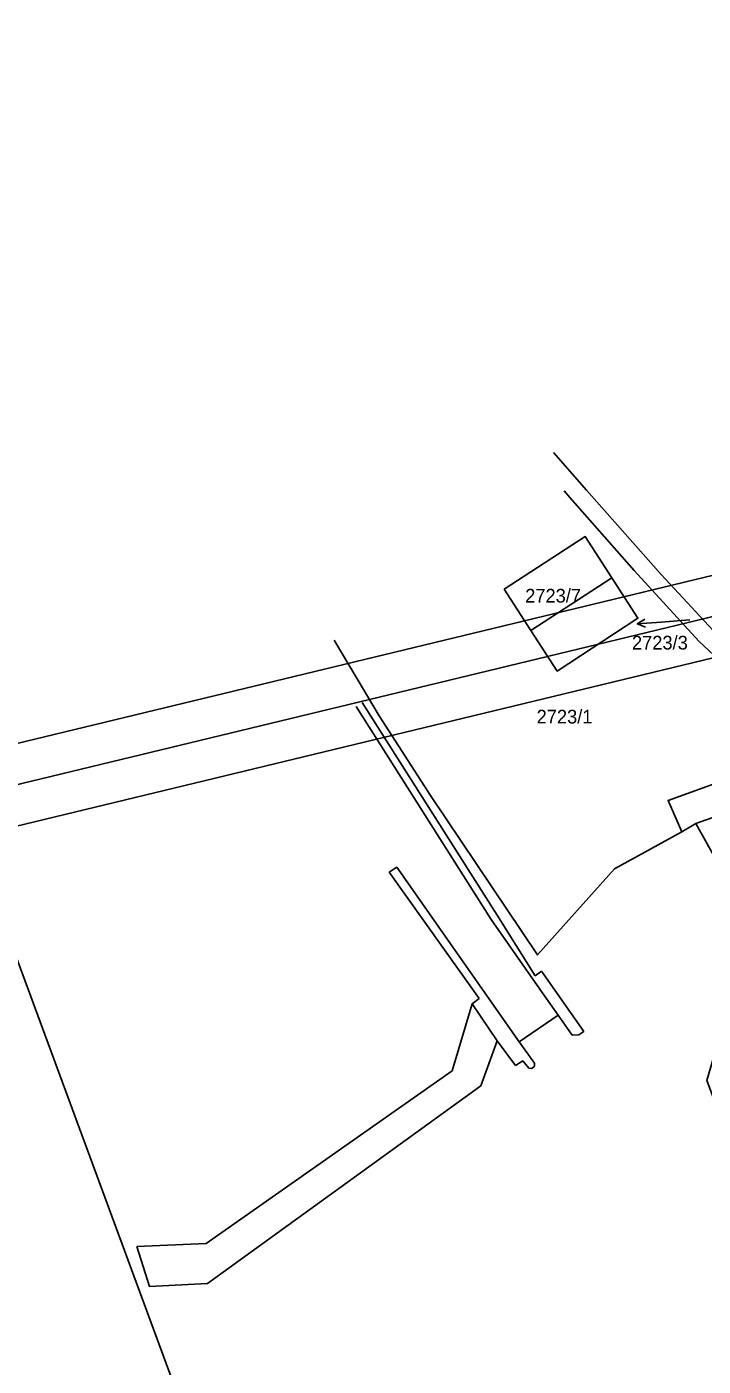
# Model space of a CAD drawing. Extents: x -738085 to -734306, y -1122197 to -1119753.
# Drawn here: x -735309.7 to -735225.5, y -1120249.4 to -1120082.8 of the extents above; entities that cross this region are included whole.
import ezdxf

# ---------------------------------------------------------------- set-up
doc = ezdxf.new("R2010")
doc.units = 0
for name, color, linetype in [('Hranice parcel', 7, 'Continuous'), ('Parcelní čísla', 7, 'Continuous'), ('Pop  PČ popisy', 7, 'Continuous'), ('Vnitřní kresba', 7, 'Continuous'), ('Vrstva 1', 7, 'Continuous')]:
    doc.layers.add(name, color=color, linetype=linetype)

msp = doc.modelspace()

# ---------------------------------------------------------------- linework, layer by layer
at = {"layer": 'Hranice parcel'}
for q in [(-735214.89, -1120177.8), (-735228.19, -1120182.96)]:
    msp.add_line((-735226.43, -1120181.92), q, dxfattribs=at)
for points in [[(-735290.18, -1120254.92), (-735317.57, -1120180.85), (-735339.79, -1120142.5), (-735361.49, -1120104.8), (-735379.62, -1120073.45), (-735392.28, -1120051.31)], [(-735290.18, -1120254.92), (-735317.57, -1120180.85), (-735339.79, -1120142.5), (-735361.49, -1120104.8), (-735379.62, -1120073.45), (-735392.28, -1120051.31)], [(-735193.9, -1120180.77), (-735196.33, -1120174.06), (-735197.48, -1120172.4), (-735199.22, -1120171.31), (-735200.58, -1120170.92), (-735204.03, -1120169.95), (-735208.93, -1120168.56), (-735215.43, -1120165.33), (-735220.17, -1120161.76), (-735223.18, -1120159.07), (-735230.74, -1120150.98), (-735240.02, -1120140.46), (-735244.13, -1120135.8)], [(-735207.77, -1120171.07), (-735211.09, -1120169.95), (-735216.45, -1120167.23), (-735220.95, -1120164.02), (-735226.04, -1120159.26), (-735234.12, -1120150.47), (-735242.12, -1120141.37), (-735242.83, -1120140.56)], [(-735250.29, -1120152.79), (-735240.22, -1120146.25), (-735236.9, -1120151.38), (-735233.63, -1120156.4), (-735243.68, -1120162.97), (-735246.97, -1120157.91), (-735250.29, -1120152.79)], [(-735228.19, -1120182.96), (-735236.55, -1120187.57), (-735246.14, -1120198.27), (-735259.45, -1120178.43), (-735265.84, -1120168.52), (-735271.46, -1120159.13)], [(-735228.19, -1120182.96), (-735229.89, -1120179.07), (-735207.77, -1120171.07)], [(-735226.43, -1120181.92), (-735221.97, -1120189.91), (-735220.76, -1120199.13), (-735225.06, -1120213.91), (-735220.47, -1120226.11), (-735217.93, -1120231.25)]]:
    msp.add_lwpolyline(points, dxfattribs=at)
at = {"layer": 'Pop  PČ popisy'}
for p, q in [((-735233.73, -1120157.08), (-735232.77, -1120156.51)), ((-735230.74, -1120156.87), (-735233.73, -1120157.08)), ((-735233.73, -1120157.08), (-735232.7, -1120157.51)), ((-735227.16, -1120156.6), (-735230.74, -1120156.87))]:
    msp.add_line(p, q, dxfattribs=at)
at = {"layer": 'Vnitřní kresba'}
for p, q in [((-735236.9, -1120151.38), (-735246.97, -1120157.91)), ((-735268.71, -1120167.38), (-735251.91, -1120193.87)), ((-735267.95, -1120166.9), (-735251.17, -1120193.35)), ((-735264.59, -1120187.99), (-735263.64, -1120187.35)), ((-735263.64, -1120187.35), (-735248.42, -1120209.08)), ((-735264.59, -1120187.99), (-735253.4, -1120203.71)), ((-735251.91, -1120193.87), (-735245.55, -1120202.96)), ((-735251.17, -1120193.35), (-735246.44, -1120200.88)), ((-735246.44, -1120200.88), (-735245.64, -1120200.28)), ((-735245.64, -1120200.28), (-735240.37, -1120207.79)), ((-735256.75, -1120212.71), (-735254.25, -1120204.36)), ((-735254.25, -1120204.36), (-735253.4, -1120203.71)), ((-735254.25, -1120204.36), (-735251.16, -1120208.96)), ((-735245.55, -1120202.96), (-735243.58, -1120205.77)), ((-735248.42, -1120209.08), (-735243.58, -1120205.77)), ((-735243.58, -1120205.77), (-735241.84, -1120208.25)), ((-735240.98, -1120208.23), (-735240.37, -1120207.79)), ((-735253.19, -1120214.56), (-735251.16, -1120208.96)), ((-735251.16, -1120208.96), (-735248.88, -1120212.03)), ((-735248.42, -1120209.08), (-735246.51, -1120211.75)), ((-735241.84, -1120208.25), (-735240.98, -1120208.23)), ((-735287.37, -1120234.17), (-735256.75, -1120212.71)), ((-735248.88, -1120212.03), (-735247.98, -1120211.43)), ((-735247.98, -1120211.43), (-735247.23, -1120212.35)), ((-735247.23, -1120212.35), (-735246.86, -1120212.39)), ((-735246.86, -1120212.39), (-735246.51, -1120212.13)), ((-735246.51, -1120211.75), (-735246.51, -1120212.13)), ((-735287.2, -1120239.16), (-735253.19, -1120214.56)), ((-735295.99, -1120234.54), (-735287.37, -1120234.17)), ((-735295.99, -1120234.54), (-735294.43, -1120239.51)), ((-735294.43, -1120239.51), (-735287.2, -1120239.16))]:
    msp.add_line(p, q, dxfattribs=at)
at = {"layer": 'Vrstva 1'}
for points in [[(-734534.27, -1119984.39), (-735554.91, -1120230.88), (-735485.2, -1120519.57), (-734464.55, -1120273.08)], [(-734470.58, -1120269.4), (-735481.51, -1120513.53), (-735548.88, -1120234.56), (-734537.95, -1119990.43)], [(-734541.63, -1119996.45), (-735348.44, -1120191.3), (-735283.42, -1120460.56), (-734476.61, -1120265.71)]]:
    msp.add_lwpolyline(points, close=True, dxfattribs=at)

# ---------------------------------------------------------------- texts
at = {"layer": 'Parcelní čísla'}
for s, p in [('2723/7', (-735247.67, -1120154.45)), ('2723/3', (-735234.38, -1120160.29)), ('2723/1', (-735246.25, -1120169.49))]:
    msp.add_text(s, height=1.7, dxfattribs=at).set_placement(p)

doc.saveas('drawing.dxf')
